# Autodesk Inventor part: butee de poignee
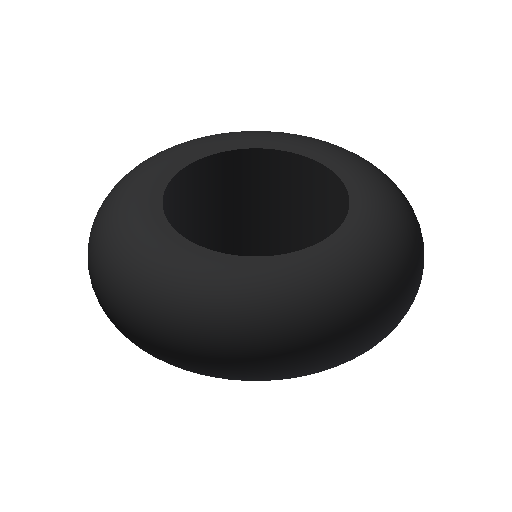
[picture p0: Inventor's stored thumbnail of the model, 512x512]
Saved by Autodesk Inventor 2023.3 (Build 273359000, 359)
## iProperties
Created: 2002-04
Part Number: butee de poignee
Material: Générique
Document SubType Name: Modélisation
Designer: Administrateur
Density: 1 g/cm^3
Appearance: Caoutchouc (Noir)
Control State: 0
Master: False
Checked Out: False
Shininess: 20.0
Angle Display Precision: 2
Document Length Units: 11269
Document Angle Units: 11279
Document Time Units: 11290
Document Mass Units: 11283
Document Length Units Precision: 3
Document Angle Units Precision: 2
Density: 0.0
Volumn: 0.0
Area: 0.0
PropertySet Name: Model Information
Author: Administrateur
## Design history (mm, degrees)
sketch "Esquisse1"
  geometry: C1 r 9 at (-11.503, 8.217); C2 r 5 at (-11.503, 8.217)
  constraints: 2 centre point, 1 coincident
  dimensions: "d0" = 10 diameter of C2; "d1" = 18 diameter of C1
extrude "Extrusion1" new body sketch "Esquisse1" distance "d2" = 7; taper "d3" = 0 deg
fillet "Congé1" dims "d4" = 3.5
node "Solide1"
node "Corps solides"
node "Corps surfaciques"
